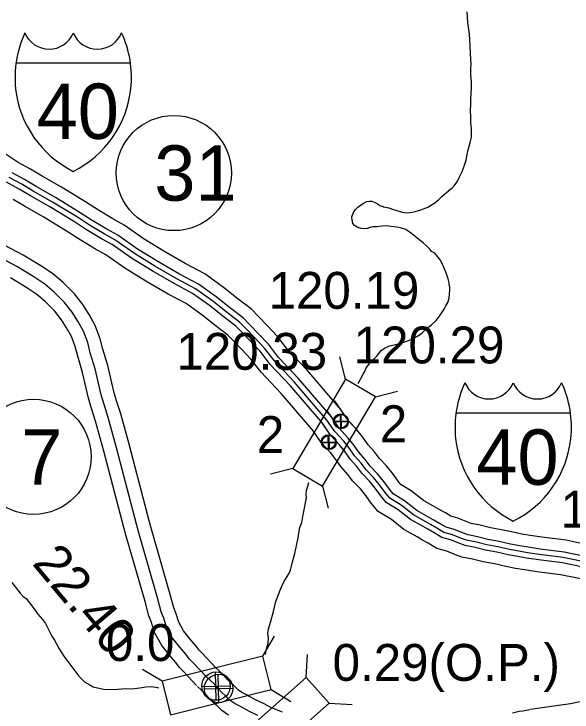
# Model space of a CAD drawing. Extents: x 31699 to 244310, y -8841 to 11474.
# Drawn here: x 102556 to 102983, y 2221 to 2754 of the extents above; entities that cross this region are included whole.
import ezdxf

# ---------------------------------------------------------------- set-up
doc = ezdxf.new("R2010")
doc.units = 0
for name, color, linetype in [('B_Logo', 7, 'Continuous'), ('Level 21', 7, 'Continuous'), ('New Level (0)', 7, 'Continuous'), ('R_Border Notes', 7, 'Continuous'), ('R_Logo', 7, 'Continuous'), ('R_No Plot', 7, 'Continuous'), ('R_XS_EARTHWORK_STAGE1', 7, 'Continuous'), ('S_AREA_CALC', 7, 'Continuous'), ('S_WALL', 7, 'Continuous'), ('S_WALL_ANNOT', 7, 'Continuous')]:
    doc.layers.add(name, color=color, linetype=linetype)

msp = doc.modelspace()

# ---------------------------------------------------------------- linework, layer by layer
at = {"layer": 'B_Logo'}
for points in [[(102795.28, 2443.86), (102770.24, 2472.97), (102755.13, 2488.97), (102747.36, 2499.1), (102740.01, 2506.9), (102733.67, 2513.37), (102728.55, 2518.65), (102719.21, 2525.7), (102708.12, 2534.52), (102694.89, 2544.05), (102680.55, 2551.7), (102663.85, 2561.4), (102648.22, 2570.91), (102633.31, 2581.42), (102625.06, 2585.94), (102613.79, 2592.76), (102604.6, 2598.66), (102585.68, 2610.27), (102570.93, 2618.65), (102562.21, 2623.9), (102552.56, 2629.06)], [(102649.87, 2364.36), (102634.55, 2422.72), (102628.16, 2445.69), (102625.05, 2455.67), (102622.84, 2463), (102618.29, 2482.85), (102614.48, 2495.23), (102612.53, 2502.96), (102609.24, 2511.81), (102604.95, 2519.37), (102600.68, 2526.14), (102594.8, 2533.49), (102586.92, 2541.61), (102579.65, 2547.67), (102571.33, 2553.26), (102558.38, 2561.06), (102544.44, 2568.45)], [(102810.44, 2424.75), (102808.13, 2427.63), (102801.35, 2435.01), (102795.28, 2443.86)], [(102861.55, 2371.39), (102852.12, 2378.82), (102843.24, 2384.16), (102839.78, 2388.38), (102835.56, 2394.26), (102830.87, 2400), (102825.25, 2405.92), (102821.37, 2411), (102816.36, 2416.6), (102812, 2422.81), (102808.13, 2427.63), (102801.35, 2435.01), (102795.28, 2443.86)], [(102948.45, 2342.52), (102941.85, 2343.65), (102934.75, 2345.06), (102925.97, 2347.03), (102917.47, 2348.53), (102909.48, 2350.59), (102902.05, 2352.06), (102898.21, 2353.42), (102891.14, 2356.24), (102884.7, 2358.06), (102879.28, 2361.32), (102874.48, 2364), (102870.89, 2366.1), (102861.55, 2371.39)], [(102703.04, 2247.87), (102692.94, 2258.76), (102690.09, 2261.49), (102687.54, 2264.91), (102684.12, 2268.9), (102677.41, 2277.22), (102672.83, 2285.59), (102670.6, 2292.48), (102668.76, 2297.45), (102665.93, 2308), (102651.55, 2357.79), (102649.87, 2364.36)], [(102703.04, 2247.87), (102692.94, 2258.76), (102690.09, 2261.49), (102687.54, 2264.91), (102684.12, 2268.9), (102677.41, 2277.22), (102672.83, 2285.59), (102670.6, 2292.48), (102668.76, 2297.45), (102665.93, 2308), (102651.55, 2357.79), (102649.87, 2364.36)], [(103246.66, 2314.29), (103192.82, 2317.68), (103159.91, 2319.15), (103114.6, 2321.71), (103090.08, 2322.88), (103067.56, 2324.57), (103051.08, 2326.17), (103033.86, 2328.83), (103021.24, 2330.84), (103002.01, 2333.72), (102989.32, 2336.07), (102975.88, 2338.8), (102957.6, 2341.1), (102948.45, 2342.52)], [(102719.59, 2231.54), (102717.28, 2233.77), (102714.96, 2235.64), (102712.08, 2238.77), (102709.32, 2242.16), (102703.04, 2247.87)], [(102742.42, 2218.23), (102736.14, 2221.19), (102729.24, 2225.08), (102725.19, 2227.11), (102721.45, 2229.74), (102717.28, 2233.77), (102714.96, 2235.64), (102712.08, 2238.77), (102709.32, 2242.16), (102703.04, 2247.87)]]:
    msp.add_lwpolyline(points, dxfattribs=at)
at = {"layer": 'Level 21'}
for p, q in [((102805.96, 2437.75), (102805.71, 2448.6)), ((102806.45, 2437.14), (102806.2, 2447.99)), ((102800.41, 2443.05), (102811.26, 2443.3)), ((102800.9, 2442.44), (102811.75, 2442.69)), ((102796.54, 2421.75), (102796.29, 2432.6)), ((102797.16, 2421.22), (102796.91, 2432.07)), ((102790.99, 2427.05), (102801.84, 2427.3)), ((102791.61, 2426.52), (102802.46, 2426.77)), ((102710.76, 2229.78), (102710.26, 2251.48)), ((102712.75, 2227.95), (102712.25, 2249.64)), ((102699.66, 2240.38), (102721.35, 2240.88)), ((102701.65, 2238.54), (102723.35, 2239.05))]:
    msp.add_line(p, q, dxfattribs=at)
for centre, radius in [((102805.84, 2443.17), 5.43), ((102806.33, 2442.57), 5.43), ((102796.41, 2427.17), 5.43), ((102797.04, 2426.65), 5.43), ((102710.51, 2240.63), 10.85), ((102712.5, 2238.8), 10.85)]:
    msp.add_circle(centre, radius, dxfattribs=at)
at = {"layer": 'New Level (0)'}
for points in [[(102805.97, 2451.89), (102780.14, 2481.9), (102765.3, 2497.62), (102757.53, 2507.75), (102749.63, 2516.13), (102743.23, 2522.67), (102737.41, 2528.68), (102727.38, 2536.24), (102716.17, 2545.15), (102701.96, 2555.4), (102687.03, 2563.36), (102670.66, 2572.86), (102655.53, 2582.06), (102640.38, 2592.76), (102631.72, 2597.5), (102620.85, 2604.07), (102611.69, 2609.96), (102592.46, 2621.75), (102577.66, 2630.16), (102568.8, 2635.49), (102559.33, 2640.56), (102549.33, 2647.02)], [(102798.44, 2446.58), (102773.33, 2475.76), (102758.31, 2491.67), (102750.54, 2501.8), (102743.02, 2509.78), (102736.66, 2516.28), (102731.32, 2521.79), (102721.76, 2528.99), (102710.64, 2537.84), (102697.1, 2547.6), (102682.57, 2555.35), (102665.98, 2564.98), (102650.5, 2574.39), (102635.52, 2584.97), (102627.14, 2589.55), (102616, 2596.29), (102606.82, 2602.19), (102587.8, 2613.86), (102573.03, 2622.25), (102564.27, 2627.52), (102554.68, 2632.65)], [(102792.13, 2441.14), (102767.14, 2470.18), (102751.96, 2486.26), (102744.18, 2496.39), (102737, 2504.01), (102730.69, 2510.46), (102725.79, 2515.52), (102716.66, 2522.4), (102705.6, 2531.2), (102692.68, 2540.51), (102678.52, 2548.06), (102661.72, 2557.82), (102645.93, 2567.42), (102631.1, 2577.88), (102622.98, 2582.33), (102611.59, 2589.22), (102602.38, 2595.13), (102583.56, 2606.68), (102568.83, 2615.05), (102560.15, 2620.27), (102550.44, 2625.47)], [(102785.18, 2435.17), (102760.33, 2464.04), (102744.97, 2480.31), (102737.19, 2490.44), (102730.39, 2497.66), (102724.12, 2504.07), (102719.7, 2508.63), (102711.05, 2515.15), (102700.07, 2523.89), (102687.82, 2532.71), (102674.06, 2540.05), (102657.03, 2549.94), (102640.9, 2559.75), (102626.24, 2570.09), (102618.41, 2574.38), (102606.74, 2581.44), (102597.51, 2587.37), (102578.9, 2598.79), (102564.2, 2607.14), (102555.62, 2612.3)], [(102869, 2382.49), (102859.71, 2389.81), (102852.09, 2394.4), (102850.36, 2396.5), (102846.15, 2402.37), (102840.89, 2408.81), (102835.42, 2414.58), (102831.66, 2419.51), (102826.82, 2424.91), (102822.66, 2430.83), (102818.24, 2436.33), (102811.81, 2443.33), (102801.17, 2458.86)], [(102863.88, 2374.86), (102854.49, 2382.25), (102846.01, 2387.36), (102843.08, 2390.92), (102838.87, 2396.79), (102834, 2402.75), (102828.43, 2408.63), (102824.59, 2413.66), (102819.63, 2419.2), (102815.33, 2425.32), (102811.29, 2430.35), (102804.62, 2437.61), (102795.74, 2450.57)], [(102818.03, 2436.56), (102811.81, 2443.33), (102806.03, 2451.77)], [(102859.22, 2367.92), (102849.75, 2375.38), (102840.48, 2380.96), (102836.47, 2385.84), (102832.25, 2391.72), (102827.74, 2397.24), (102822.07, 2403.22), (102818.16, 2408.35), (102813.09, 2414.01), (102808.67, 2420.31), (102804.97, 2424.91), (102798.08, 2432.41), (102791.17, 2442.49)], [(102813.13, 2428.05), (102811.29, 2430.35), (102804.62, 2437.61), (102798.72, 2446.22)], [(102808.57, 2420.43), (102804.97, 2424.91), (102798.08, 2432.41), (102791.85, 2441.51)], [(102803.51, 2411.7), (102801.33, 2414.8), (102798.01, 2418.93), (102790.89, 2426.69), (102784.28, 2436.33)], [(102854.1, 2360.29), (102844.53, 2367.82), (102834.39, 2373.92), (102829.2, 2380.25), (102824.97, 2386.15), (102820.86, 2391.18), (102815.08, 2397.26), (102811.09, 2402.5), (102805.9, 2408.3), (102801.33, 2414.8), (102798.01, 2418.93), (102790.89, 2426.69), (102786.08, 2433.71)], [(102950.7, 2355.66), (102944.27, 2356.76), (102937.51, 2358.11), (102928.59, 2360.1), (102920.3, 2361.57), (102912.44, 2363.6), (102905.6, 2364.95), (102902.92, 2365.9), (102895.44, 2368.88), (102890.05, 2370.41), (102885.96, 2372.86), (102881.09, 2375.57), (102877.55, 2377.65), (102869, 2382.49)], [(102949.16, 2346.63), (102942.61, 2347.75), (102935.61, 2349.14), (102926.79, 2351.11), (102918.35, 2352.61), (102910.41, 2354.65), (102903.16, 2356.09), (102899.68, 2357.32), (102892.48, 2360.19), (102886.37, 2361.92), (102881.37, 2364.93), (102876.54, 2367.61), (102872.97, 2369.71), (102863.88, 2374.86)], [(102947.75, 2338.41), (102941.09, 2339.55), (102933.89, 2340.98), (102925.15, 2342.94), (102916.58, 2344.46), (102908.56, 2346.52), (102900.94, 2348.03), (102896.74, 2349.52), (102889.8, 2352.29), (102883.03, 2354.21), (102877.19, 2357.72), (102872.41, 2360.38), (102868.81, 2362.49), (102859.22, 2367.92)], [(102946.21, 2329.38), (102939.43, 2330.54), (102931.99, 2332.01), (102923.35, 2333.95), (102914.64, 2335.49), (102906.53, 2337.58), (102898.5, 2339.17), (102893.51, 2340.94), (102886.85, 2343.59), (102879.35, 2345.72), (102872.6, 2349.78), (102867.86, 2352.42), (102864.23, 2354.55), (102854.1, 2360.29)], [(103341.29, 2323.55), (103310.97, 2324.76), (103247.38, 2327.6), (103193.53, 2330.99), (103160.58, 2332.47), (103115.3, 2335.02), (103090.9, 2336.19), (103068.7, 2337.85), (103052.75, 2339.4), (103035.93, 2342), (103023.28, 2344.02), (103004.21, 2346.88), (102991.86, 2349.16), (102978.05, 2351.97), (102959.45, 2354.31), (102950.5, 2355.7)], [(103340.77, 2314.39), (103310.59, 2315.6), (103246.88, 2318.45), (103193.04, 2321.84), (103160.12, 2323.31), (103114.82, 2325.87), (103090.34, 2327.04), (103067.91, 2328.72), (103051.6, 2330.31), (103034.5, 2332.94), (103021.88, 2334.96), (103002.7, 2337.83), (102990.11, 2340.16), (102976.56, 2342.92), (102958.18, 2345.23), (102949.09, 2346.64)], [(103340.35, 2306.07), (103310.23, 2307.27), (103246.44, 2310.13), (103192.59, 2313.52), (103159.7, 2314.99), (103114.38, 2317.55), (103089.83, 2318.72), (103067.2, 2320.41), (103050.56, 2322.03), (103033.21, 2324.71), (103020.6, 2326.72), (103001.32, 2329.61), (102988.52, 2331.98), (102975.21, 2334.69), (102957.02, 2336.98), (102947.82, 2338.4)], [(103339.91, 2296.91), (103309.85, 2298.11), (103245.94, 2300.97), (103192.1, 2304.36), (103159.23, 2305.83), (103113.91, 2308.39), (103089.27, 2309.57), (103066.41, 2311.28), (103049.42, 2312.93), (103031.79, 2315.65), (103019.2, 2317.66), (102999.81, 2320.57), (102986.78, 2322.98), (102973.72, 2325.64), (102955.75, 2327.9), (102946.41, 2329.34)]]:
    msp.add_lwpolyline(points, dxfattribs=at)
at = {"layer": 'R_Border Notes'}
for centre in [(102678.35, 2632.48), (102571.15, 2415.72)]:
    msp.add_circle(centre, 44, dxfattribs=at)
at = {"layer": 'R_Logo'}
for points in [[(102825.82, 2610.75), (102827.56, 2610.91), (102829.69, 2610.87), (102832.1, 2610.04), (102833.98, 2609), (102836.34, 2607.44), (102837.68, 2607.06), (102838.55, 2606.67), (102842.69, 2605.86), (102846.11, 2604.51), (102848.72, 2603.82), (102852.81, 2602.61), (102856.41, 2602.2), (102860.41, 2602.53), (102862.67, 2603.03), (102867.04, 2604.3), (102872.28, 2606.52), (102876.9, 2609.26), (102880.53, 2611.99), (102883.15, 2614.56), (102885.13, 2616.33), (102888.15, 2618.91), (102890.92, 2621.23), (102892.43, 2622.65), (102894.13, 2624.75), (102894.97, 2626.23), (102896.4, 2629.06), (102898.73, 2633.57), (102900.27, 2637.6), (102901.73, 2642.3), (102902.46, 2646.65), (102903.34, 2650.13), (102904.1, 2653.08), (102904.72, 2655.83), (102905.73, 2659.85), (102905.81, 2663.13), (102905.83, 2666.4), (102905.23, 2670.73), (102905.22, 2675.74), (102905.03, 2679.88), (102905.28, 2685.42), (102905.22, 2689.36), (102905.63, 2692.71), (102905.75, 2698.05), (102905.69, 2702.19), (102905.21, 2707.59), (102905.21, 2712), (102905.42, 2715.68), (102905.3, 2719.42), (102904.9, 2723.75), (102904.68, 2729.69), (102904.61, 2734.1), (102904.14, 2738.43), (102903.62, 2742.1), (102902.94, 2747.36), (102902.74, 2751.7), (102902.42, 2755.57)], [(102825.82, 2610.75), (102827.56, 2610.91), (102829.69, 2610.87), (102832.1, 2610.04), (102833.98, 2609), (102836.34, 2607.44), (102837.68, 2607.06), (102838.55, 2606.67), (102842.69, 2605.86), (102846.11, 2604.51), (102848.72, 2603.82), (102852.81, 2602.61), (102856.41, 2602.2), (102860.41, 2602.53), (102862.67, 2603.03), (102867.04, 2604.3), (102872.28, 2606.52), (102876.9, 2609.26), (102880.53, 2611.99), (102883.15, 2614.56), (102885.13, 2616.33), (102888.15, 2618.91), (102890.92, 2621.23), (102892.43, 2622.65), (102894.13, 2624.75), (102894.97, 2626.23), (102896.4, 2629.06), (102898.73, 2633.57), (102900.27, 2637.6), (102901.73, 2642.3), (102902.46, 2646.65), (102903.34, 2650.13), (102904.1, 2653.08), (102904.72, 2655.83), (102905.73, 2659.85), (102905.81, 2663.13), (102905.83, 2666.4), (102905.23, 2670.73), (102905.22, 2675.74), (102905.03, 2679.88), (102905.28, 2685.42), (102905.22, 2689.36), (102905.63, 2692.71), (102905.75, 2698.05), (102905.69, 2702.19), (102905.21, 2707.59), (102905.21, 2712), (102905.42, 2715.68), (102905.3, 2719.42), (102904.9, 2723.75), (102904.68, 2729.69), (102904.61, 2734.1), (102904.14, 2738.43), (102903.62, 2742.1), (102902.94, 2747.36), (102902.74, 2751.7), (102902.42, 2755.57)], [(102889.11, 2545.61), (102888.83, 2547.6), (102888.68, 2548.6), (102887.9, 2551.73), (102886.58, 2555.51), (102884.29, 2561.09), (102883.67, 2562.62), (102882.02, 2566), (102877.74, 2571.27), (102875.25, 2572.57), (102874.17, 2574.02), (102871.6, 2576.59), (102868.76, 2579.22), (102864.37, 2582.62), (102862.35, 2584.19), (102859.99, 2586.29), (102855.48, 2589.23), (102851.52, 2590.64), (102848.65, 2591.2), (102844.31, 2591.66), (102840.7, 2592.08), (102837.24, 2592.02), (102833.32, 2591.36), (102830.32, 2591.32), (102828.26, 2590.82), (102826.2, 2590.12), (102823.74, 2589.95), (102821.47, 2590.11), (102818.79, 2590.94), (102816.44, 2592.37), (102815.22, 2593.89), (102814.92, 2595.62), (102814.71, 2596.49), (102814.41, 2598.69), (102814.4, 2599.09), (102814.66, 2599.89), (102815.11, 2601.04), (102815.62, 2602.45), (102816.6, 2603.8), (102817.12, 2604.54), (102818.04, 2605.62), (102818.83, 2606.37), (102819.88, 2607.25), (102820.87, 2607.94), (102822.92, 2609.17), (102824.63, 2610.33), (102825.82, 2610.75)], [(102819.21, 2471.64), (102822.88, 2478.81), (102824.18, 2481.03), (102825.41, 2483.72), (102826.59, 2485.14), (102829.2, 2488.92), (102831.18, 2490.22), (102833.08, 2492.32), (102836.74, 2496.99), (102839.31, 2498.7), (102843.15, 2500.42), (102848.86, 2501.71), (102855.57, 2503.69), (102860.87, 2505.77), (102864.43, 2507.89), (102867.93, 2510.22), (102871.48, 2513.68), (102875.3, 2516.48), (102878.85, 2519.94), (102881.33, 2523.18), (102883.29, 2526.21), (102884.79, 2528.44), (102886.28, 2530.93), (102887.71, 2533.69), (102888.66, 2536.85), (102889.07, 2540.26), (102889.3, 2543), (102889.2, 2544.94), (102888.83, 2547.6), (102888.68, 2548.6), (102887.9, 2551.73), (102886.58, 2555.51), (102884.29, 2561.09), (102883.67, 2562.62), (102882.02, 2566), (102877.74, 2571.27), (102875.25, 2572.57), (102874.17, 2574.02), (102871.6, 2576.59), (102868.76, 2579.22), (102864.37, 2582.62), (102862.35, 2584.19), (102859.99, 2586.29), (102855.48, 2589.23), (102851.52, 2590.64), (102848.65, 2591.2), (102844.31, 2591.66), (102840.7, 2592.08), (102837.24, 2592.02), (102833.32, 2591.36), (102830.32, 2591.32), (102828.26, 2590.82), (102826.2, 2590.12), (102823.74, 2589.95), (102821.47, 2590.11), (102818.79, 2590.94), (102816.44, 2592.37), (102815.22, 2593.89), (102814.92, 2595.62), (102814.71, 2596.49), (102814.41, 2598.69), (102814.4, 2599.09), (102814.66, 2599.89), (102815.11, 2601.04), (102815.62, 2602.45), (102816.6, 2603.8), (102817.12, 2604.54), (102818.04, 2605.62), (102818.83, 2606.37), (102819.88, 2607.25), (102820.87, 2607.94), (102822.92, 2609.17), (102824.63, 2610.33), (102825.82, 2610.75)], [(102819.21, 2471.64), (102822.88, 2478.81), (102824.18, 2481.03), (102825.37, 2483.64)], [(102776.78, 2370.05), (102779.72, 2384.39), (102779.55, 2386.92), (102779.77, 2390.07), (102780.78, 2393.35), (102781.41, 2396.03), (102781.5, 2396.2)], [(102776.78, 2370.05), (102779.72, 2384.39), (102779.55, 2386.92), (102779.77, 2390.07), (102780.78, 2393.35), (102781.41, 2396.03), (102781.5, 2396.2)], [(102748.38, 2264.79), (102748.99, 2268.06), (102750.37, 2273.37), (102750.6, 2277.31), (102750.23, 2281.1), (102750.74, 2284.32), (102752.38, 2290.17), (102754.44, 2297.63), (102755.15, 2300.92), (102756.05, 2304.49), (102757.72, 2309.34), (102760.09, 2315.14), (102762.49, 2320.21), (102766.18, 2326.51), (102767.5, 2329.15), (102769.06, 2335.54), (102770.89, 2341.86), (102772.42, 2349.04), (102773.29, 2353.87), (102773.79, 2357.55), (102774.68, 2361.65), (102776.04, 2365.56), (102776.78, 2370.05)], [(102748.38, 2264.79), (102748.99, 2268.06), (102750.37, 2273.37), (102750.6, 2277.31), (102750.23, 2281.1), (102750.74, 2284.32), (102752.38, 2290.17), (102754.44, 2297.63), (102755.15, 2300.92), (102756.05, 2304.49), (102757.72, 2309.34), (102760.09, 2315.14), (102762.49, 2320.21), (102766.18, 2326.51), (102767.5, 2329.15), (102769.06, 2335.54), (102770.89, 2341.86), (102772.42, 2349.04), (102773.29, 2353.87), (102773.79, 2357.55), (102774.68, 2361.65), (102776.04, 2365.56), (102776.78, 2370.05)], [(102554.58, 2319.83), (102560.8, 2311.65), (102563.27, 2309.05), (102565.51, 2307.51), (102568.13, 2304.17), (102569.72, 2302.01), (102571.25, 2299.85), (102574.43, 2295.67), (102578, 2291.62), (102580.35, 2288.48), (102581.12, 2287.04), (102582.11, 2284.99), (102583.87, 2281.44), (102585.08, 2278.8), (102587.16, 2275.65), (102590.6, 2269.14), (102594.36, 2263.5), (102597.33, 2259.37), (102601.9, 2253.29), (102605.63, 2248.32), (102610.15, 2243.9), (102613.53, 2241.79), (102616.58, 2240.2), (102624.69, 2238.29), (102632.03, 2237.95), (102641.59, 2238.87), (102646.33, 2238.6), (102652.31, 2239.3), (102656.88, 2240.09), (102661.21, 2240.34), (102665.96, 2239.6), (102666.79, 2239.39)], [(102554.58, 2319.83), (102560.8, 2311.65), (102563.27, 2309.05), (102565.51, 2307.51), (102568.13, 2304.17), (102569.72, 2302.01), (102571.25, 2299.85), (102574.43, 2295.67), (102578, 2291.62), (102580.35, 2288.48), (102581.12, 2287.04), (102582.11, 2284.99), (102583.87, 2281.44), (102585.08, 2278.8), (102587.16, 2275.65), (102590.6, 2269.14), (102594.36, 2263.5), (102597.33, 2259.37), (102601.9, 2253.29), (102605.63, 2248.32), (102610.15, 2243.9), (102613.53, 2241.79), (102616.58, 2240.2), (102624.69, 2238.29), (102632.03, 2237.95), (102641.59, 2238.87), (102646.33, 2238.6), (102652.31, 2239.3), (102656.88, 2240.09), (102661.21, 2240.34), (102665.96, 2239.6), (102666.79, 2239.39)]]:
    msp.add_lwpolyline(points, dxfattribs=at)
at = {"layer": 'R_No Plot'}
for p, q in [((102557.78, 2716.54), (102645.17, 2716.54)), ((102893.99, 2449.38), (102981.38, 2449.38))]:
    msp.add_line(p, q, dxfattribs=at)
for centre, radius, start, end in [((102638.99, 2705.16), 82.01, 155.2204, 185.7928), ((102583.04, 2747.06), 19.98, 202.1459, 337.3414), ((102619.91, 2747.06), 19.98, 202.6586, 337.8541), ((102563.96, 2705.16), 82.01, 354.2072, 24.7796), ((102637.48, 2705.85), 80.58, 186.3923, 243.4571), ((102565.47, 2705.85), 80.58, 296.5429, 353.6077), ((102975.2, 2438), 82.01, 155.2204, 185.7928), ((102919.25, 2479.9), 19.98, 202.1459, 337.3414), ((102956.12, 2479.9), 19.98, 202.6586, 337.8541), ((102900.17, 2438), 82.01, 354.2072, 24.7796), ((102973.69, 2438.69), 80.58, 186.3923, 243.4571), ((102901.68, 2438.69), 80.58, 296.5429, 353.6077)]:
    msp.add_arc(centre, radius, start, end, dxfattribs=at)
at = {"layer": 'R_XS_EARTHWORK_STAGE1'}
for p, q in [((102809.57, 2475.07), (102805.19, 2492.11)), ((102809.57, 2475.07), (102805.19, 2492.11)), ((102832.3, 2461.63), (102849.35, 2466.01)), ((102832.3, 2461.63), (102849.35, 2466.01)), ((102769.27, 2406.89), (102752.22, 2402.51)), ((102769.27, 2406.89), (102752.22, 2402.51)), ((102791.99, 2393.46), (102796.37, 2376.41)), ((102791.99, 2393.46), (102796.37, 2376.41)), ((102746.25, 2263.6), (102755.3, 2278.7)), ((102746.25, 2263.6), (102755.3, 2278.7)), ((102779.51, 2247.33), (102780.56, 2264.9)), ((102669.43, 2244.35), (102654.33, 2253.39)), ((102669.43, 2244.35), (102654.33, 2253.39)), ((102752.67, 2238), (102767.77, 2228.95)), ((102752.67, 2238), (102767.77, 2228.95)), ((102797.02, 2227.58), (102814.59, 2226.53))]:
    msp.add_line(p, q, dxfattribs=at)
for points in [[(102809.57, 2475.07), (102769.27, 2406.89), (102791.99, 2393.46), (102832.3, 2461.63)], [(102809.57, 2475.07), (102769.27, 2406.89), (102791.99, 2393.46), (102832.3, 2461.63)], [(102746.25, 2263.6), (102669.43, 2244.35), (102675.85, 2218.74), (102752.67, 2238)], [(102746.25, 2263.6), (102669.43, 2244.35), (102675.85, 2218.74), (102752.67, 2238)], [(102737.77, 2175.03), (102797.02, 2227.58), (102779.51, 2247.33), (102720.25, 2194.78)]]:
    msp.add_lwpolyline(points, close=True, dxfattribs=at)
at = {"layer": 'S_AREA_CALC'}
for points in [[(102659.54, 2366.9), (102644.2, 2425.33), (102637.76, 2448.52), (102634.61, 2458.61), (102632.51, 2465.57), (102627.95, 2485.44), (102624.12, 2497.93), (102622.09, 2505.94), (102618.33, 2516.04), (102613.54, 2524.51), (102608.84, 2531.95), (102602.31, 2540.11), (102593.73, 2548.95), (102585.66, 2555.69), (102576.7, 2561.7), (102563.31, 2569.76), (102549.18, 2577.25)], [(102640.2, 2361.83), (102624.9, 2420.11), (102618.57, 2442.86), (102615.49, 2452.74), (102613.17, 2460.43), (102608.62, 2480.26), (102604.85, 2492.54), (102602.97, 2499.98), (102600.14, 2507.57), (102596.37, 2514.24), (102592.52, 2520.33), (102587.29, 2526.86), (102580.11, 2534.27), (102573.65, 2539.66), (102565.96, 2544.82), (102553.46, 2552.35)], [(102695.7, 2241.07), (102685.81, 2251.74), (102682.57, 2254.85), (102679.73, 2258.66), (102676.43, 2262.5), (102669.07, 2271.64), (102663.6, 2281.62), (102661.15, 2289.21), (102659.23, 2294.4), (102656.29, 2305.31), (102641.9, 2355.17), (102640.18, 2361.89)], [(102710.37, 2254.66), (102700.08, 2265.77), (102697.61, 2268.14), (102695.36, 2271.15), (102691.81, 2275.29), (102685.75, 2282.81), (102682.05, 2289.56), (102680.06, 2295.76), (102678.3, 2300.49), (102675.56, 2310.68), (102661.2, 2360.42), (102659.56, 2366.84)], [(102735.93, 2232.79), (102733.93, 2233.91), (102730.34, 2235.71), (102727.84, 2237.47), (102723.91, 2241.27), (102721.82, 2242.96), (102719.64, 2245.31), (102716.6, 2249.06), (102709.76, 2255.27)], [(102761.36, 2220.82), (102753.04, 2224.14), (102746.76, 2227.23), (102740.74, 2230.08), (102733.93, 2233.91), (102730.34, 2235.71), (102727.84, 2237.47), (102723.91, 2241.27), (102721.82, 2242.96), (102719.64, 2245.31), (102716.6, 2249.06), (102709.76, 2255.27)], [(102710.5, 2226.39), (102708.11, 2228.32), (102704.51, 2232.22), (102702.04, 2235.27), (102696.32, 2240.46)], [(102720.04, 2218.5), (102715.06, 2222.01), (102710.65, 2226.27), (102708.11, 2228.32), (102704.51, 2232.22), (102702.04, 2235.27), (102696.32, 2240.46)], [(102994.85, 2229.79), (102981.32, 2226.98), (102972.21, 2225.76), (102950.93, 2222.73)], [(102950.38, 2222.63), (102944.96, 2221.55), (102942.23, 2221.13), (102937.2, 2219.96)]]:
    msp.add_lwpolyline(points, dxfattribs=at)

# ---------------------------------------------------------------- texts
at = {"layer": 'R_Border Notes'}
for s, p in [('31', (102663.39, 2611.36)), ('7', (102561.7, 2394.6))]:
    msp.add_text(s, height=42.24, dxfattribs=at).set_placement(p)
at = {"layer": 'R_No Plot'}
for p in [(102573.54, 2658.55), (102909.48, 2394.39)]:
    msp.add_text('40', height=42.24, dxfattribs=at).set_placement(p)
at = {"layer": 'R_XS_EARTHWORK_STAGE1'}
for p in [(102835.7, 2426.92), (102741.7, 2418.68)]:
    msp.add_text('2', height=28.16, dxfattribs=at).set_placement(p)
at = {"layer": 'S_WALL'}
for s, p in [('120.19', (102750.71, 2528.78)), ('122.27', (102973.93, 2361.68)), ('0.29(O.P.)', (102799.63, 2244.65))]:
    msp.add_text(s, height=28.16, dxfattribs=at).set_placement(p)
msp.add_text('22.40', height=28.16, rotation=310, dxfattribs=at).set_placement((102569.41, 2334.09))
at = {"layer": 'S_WALL_ANNOT'}
for s, p in [('120.29', (102815.73, 2487.09)), ('120.33', (102680.3, 2482.18)), ('0.0', (102626.42, 2259.81))]:
    msp.add_text(s, height=28.16, dxfattribs=at).set_placement(p)

doc.saveas('drawing.dxf')
